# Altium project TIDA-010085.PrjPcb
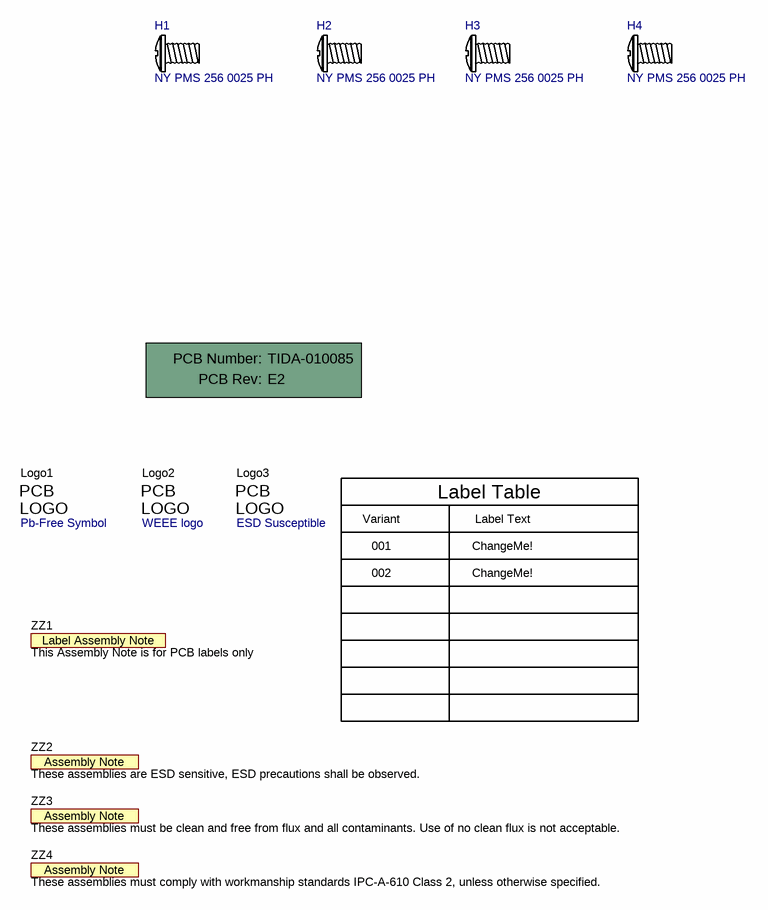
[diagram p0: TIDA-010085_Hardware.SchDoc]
CopyrightYear: 2021; EVM_orderable: N/A; PCB_Layout: Manu; PCB_Rev: E2; PRJ_Customer: Public Release; PRJ_Engineer: Manu Balakrishnan; PRJ_Number: TIDA-010085; PRJ_Title: 24-VAC Multi-channel Solid State Relay; SCH_Rev: E2; TechSupport: http://www.ti.com/support; TID: 010085
4 sheets, 249 parts. Net scope: flat (ports and power ports of the same name join across sheets).
Board file: TIDA-010085.PcbDoc
Sheets:
  TIDA-010085_CoverSheet.SchDoc
  TIDA-010085_Hardware.SchDoc
  TIDA-010085_Page1.SchDoc
  TIDA-010085_Page2.SchDoc

## Sheet TIDA-010085_CoverSheet.SchDoc
size 431 x 279 mm; Date: Not shown in title block; ApprovedBy: Not shown in title block; CheckedBy: Not shown in title block; Author: Not shown in title block; CompanyName: Not shown in title block; DrawnBy: Manu; Engineer: Not shown in title block; Organization: Not shown in title block; Address1: Not shown in title block; Address2: Not shown in title block; Address3: Not shown in title block; Address4: Not shown in title block; DocumentNumber: 1; Revision: Use project parameter SCH_Rev; SheetNumber: 1; SheetTotal: 4; PageSetup: Record=PageOptions¦CenterHorizontal=True¦CenterVertical=True¦PrintScale=1.00¦XCorrection=1.00¦YCorrection=1.00¦PrintKind=0¦BorderSize=5000000¦LeftOffset=0¦BottomOffset=0¦Orientation=2¦PaperLength=1000¦PaperWidth=1000¦Scale=100¦PaperSource=15¦PrintQuality=600¦MediaType=1¦DitherType=10¦PaperKind=Letter¦PrintScaleMode=1

## Sheet TIDA-010085_Hardware.SchDoc
size 431 x 279 mm; Date: Not shown in title block; ApprovedBy: Not shown in title block; CheckedBy: Not shown in title block; Author: Not shown in title block; CompanyName: Not shown in title block; DrawnBy: Manu; Engineer: Not shown in title block; Organization: Not shown in title block; Address1: Not shown in title block; Address2: Not shown in title block; Address3: Not shown in title block; Address4: Not shown in title block; DocumentNumber: 1; Revision: Use project parameter SCH_Rev; SheetNumber: 4; SheetTotal: 4; PageSetup: Record=PageOptions¦CenterHorizontal=True¦CenterVertical=True¦PrintScale=1.00¦XCorrection=1.00¦YCorrection=1.00¦PrintKind=0¦BorderSize=5000000¦LeftOffset=0¦BottomOffset=0¦Orientation=2¦PaperLength=1000¦PaperWidth=1000¦Scale=100¦PaperSource=15¦PrintQuality=600¦MediaType=1¦DitherType=10¦PaperKind=Letter¦PrintScaleMode=1

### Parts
!PCB1  Printed Circuit Board  (value not drawn)  (mechanical)
H1  NY PMS 256 0025 PH  [NY PMS 256 0025 PH]
H2  NY PMS 256 0025 PH  [NY PMS 256 0025 PH]
H3  NY PMS 256 0025 PH  [NY PMS 256 0025 PH]
H4  NY PMS 256 0025 PH  [NY PMS 256 0025 PH]
Logo1  Pb-Free Symbol  [Pb-Free_Overlay_Small]  (no BOM)
Logo2  WEEE logo  [WEEE_Minimum]  (no BOM)
Logo3  ESD Susceptible  [ESD_Overlay_Small]  (no BOM)
ZZ1  This Assembly Note is for PCB labels only  [AssemblyNoteLabel]  (no BOM)
ZZ2  These assemblies are ESD sensitive, ESD precautions shall be observed.  [AssemblyNote]  (no BOM)
ZZ3  These assemblies must be clean and free from flux and all contaminants. Use of no clean flux is not acceptable.  [AssemblyNote]  (no BOM)
ZZ4  These assemblies must comply with workmanship standards IPC-A-610 Class 2, unless otherwise specified.  [AssemblyNote]  (no BOM)

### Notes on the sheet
- Variant
- 001
- Label Table
- Label Text
- ChangeMe!
- 002

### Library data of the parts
!PCB1 = PCB: Manufacturer: Any; PartNumber: TIDA-010085; SymbolCreator: a0412235
H1-H4 = CMP-0003709-1: MACHINE SCREW PAN PHILLIPS 2-56; Manufacturer: B&F Fastener Supply; CompType: Hardware
Logo1 = CMP-0074839-1: SymbolCreator: a0412235
Logo2 = CMP-0074769-1
Logo3 = CMP-0074840-1: ESD Susceptible Symbol; SymbolCreator: a0412235; Lib Reference: ESD_Susceptible
ZZ1 = AssemblyNoteLabel: SymbolCreator: a0412235
ZZ2-ZZ4 = AssemblyNote: SymbolCreator: codlsc

## Sheet TIDA-010085_Page1.SchDoc
size 431 x 279 mm; Date: Not shown in title block; ApprovedBy: Not shown in title block; CheckedBy: Not shown in title block; Author: Not shown in title block; CompanyName: Not shown in title block; DrawnBy: Manu; Engineer: Not shown in title block; Organization: Not shown in title block; Address1: Not shown in title block; Address2: Not shown in title block; Address3: Not shown in title block; Address4: Not shown in title block; DocumentNumber: 1; Revision: Use project parameter SCH_Rev; SheetNumber: 2; SheetTotal: 4; PageSetup: Record=PageOptions¦CenterHorizontal=True¦CenterVertical=True¦PrintScale=1.00¦XCorrection=1.00¦YCorrection=1.00¦PrintKind=0¦BorderSize=5000000¦LeftOffset=0¦BottomOffset=0¦Orientation=2¦PaperLength=1000¦PaperWidth=1000¦Scale=100¦PaperSource=15¦PrintQuality=600¦MediaType=1¦DitherType=10¦PaperKind=Letter¦PrintScaleMode=1
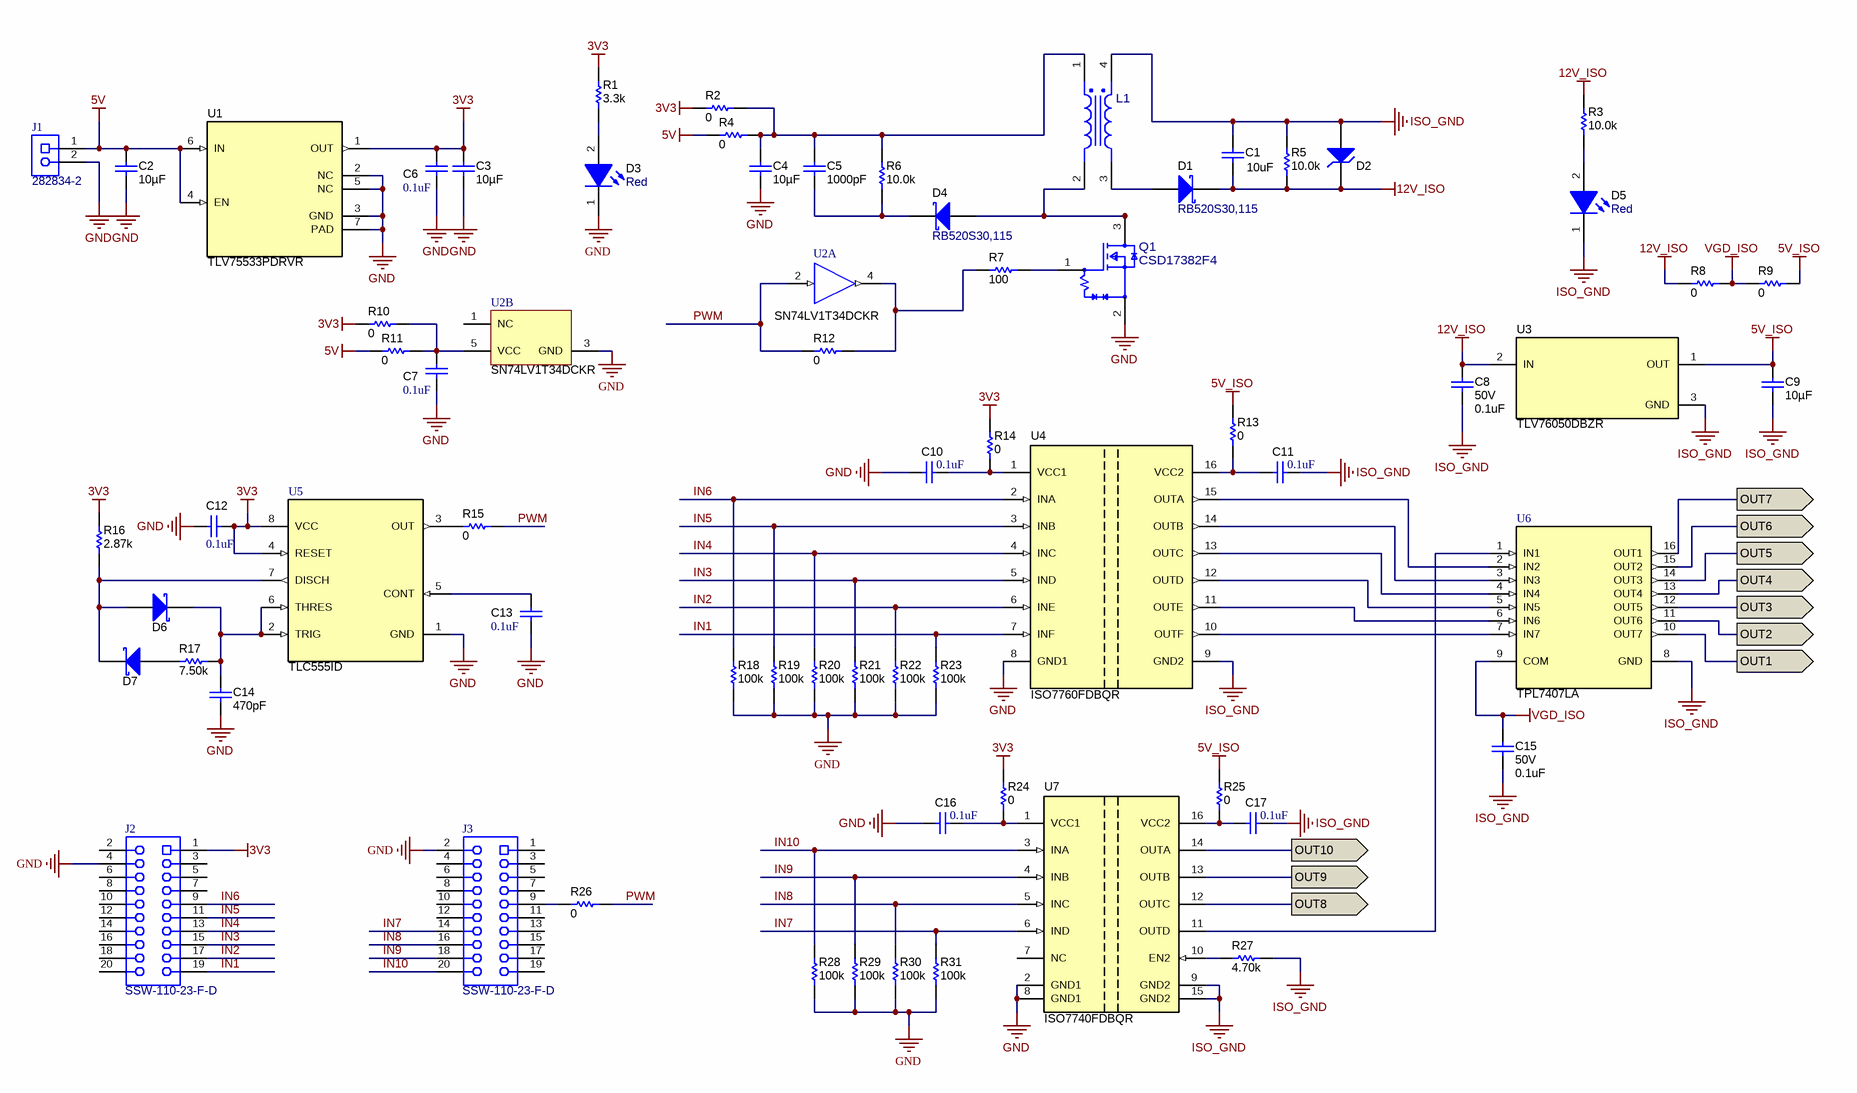
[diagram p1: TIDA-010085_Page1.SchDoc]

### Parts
C1  ValueDisplayed: 10uF  [0603]  (hidden comment: GRM188R61E106MA73D)
C2  ValueDisplayed: 10µF  [0603]  (hidden comment: GRM188R61A106KE69D)
C3  ValueDisplayed: 10µF  [0603]  (hidden comment: GRM188R61A106KE69D)
C4  ValueDisplayed: 10µF  [0603]  (hidden comment: GRM188R61A106KE69D)
C5  ValueDisplayed: 1000pF  [0402]  (hidden comment: 885012205061)
C6  ValueDisplayed: 0.1uF  [0402]  (hidden comment: GCM155R71A104KA55D)
C7  ValueDisplayed: 0.1uF  [0402]  (hidden comment: GCM155R71A104KA55D)
C8  VDC_V: 50V  ValueDisplayed: 0.1uF  [0402]  (hidden comment: GRM155R71H104ME14D)
C9  ValueDisplayed: 10µF  [0603]  (hidden comment: GRM188R61A106KE69D)
C10  ValueDisplayed: 0.1uF  [0402]  (hidden comment: GCM155R71A104KA55D)
C11  ValueDisplayed: 0.1uF  [0402]  (hidden comment: GCM155R71A104KA55D)
C12  ValueDisplayed: 0.1uF  [0402]  (hidden comment: GCM155R71A104KA55D)
C13  ValueDisplayed: 0.1uF  [0402]  (hidden comment: GCM155R71A104KA55D)
C14  ValueDisplayed: 470pF  [0402]  (hidden comment: GRT155R71H471KE01D)
C15  VDC_V: 50V  ValueDisplayed: 0.1uF  [0402]  (hidden comment: GRM155R71H104ME14D)
C16  ValueDisplayed: 0.1uF  [0402]  (hidden comment: GCM155R71A104KA55D)
C17  ValueDisplayed: 0.1uF  [0402]  (hidden comment: GCM155R71A104KA55D)
D1  RB520S30,115  [SOD-523]
D2  BZT585B12T-7  [SOD-523]  (value not drawn)
D3  value Red  [WL-SMCW_RED]  (hidden comment: 150060RS75000)
D4  RB520S30,115  [SOD-523]
D5  value Red  [WL-SMCW_RED]  (hidden comment: 150060RS75000)
D6  RB520S30,115  [SOD-523]  (value not drawn)
D7  RB520S30,115  [SOD-523]  (value not drawn)
J1  282834-2  [TEC_282834-2]
J2  SSW-110-23-F-D  [CONN_SSW-110-23-F-D]
J3  SSW-110-23-F-D  [CONN_SSW-110-23-F-D]
L1  744889030330  [FP-744889020330_SMD4-MFG]  (value not drawn)
Q1  CSD17382F4  [FP-CSD17382F4_PICOSTAR3-MFG]
R1  ValueDisplayed: 3.3k  [0402]  (hidden comment: CRCW04023K30JNED)
R2  ValueDisplayed: 0  [0402]  (hidden comment: RC0402JR-070RL)
R3  ValueDisplayed: 10.0k  [0402]  (hidden comment: RMCF0402FT10K0)
R4  ValueDisplayed: 0  [0402]  (hidden comment: RC0402JR-070RL)
R5  ValueDisplayed: 10.0k  [0402]  (hidden comment: RMCF0402FT10K0)
R6  ValueDisplayed: 10.0k  [0402]  (hidden comment: RMCF0402FT10K0)
R7  ValueDisplayed: 100  [0402]  (hidden comment: RC0402FR-07100RL)
R8  ValueDisplayed: 0  [0402]  (hidden comment: RC0402JR-070RL)
R9  ValueDisplayed: 0  [0402]  (hidden comment: RC0402JR-070RL)
R10  ValueDisplayed: 0  [0402]  (hidden comment: RC0402JR-070RL)
R11  ValueDisplayed: 0  [0402]  (hidden comment: RC0402JR-070RL)
R12  ValueDisplayed: 0  [0402]  (hidden comment: RC0402JR-070RL)
R13  ValueDisplayed: 0  [0402]  (hidden comment: RC0402JR-070RL)
R14  ValueDisplayed: 0  [0402]  (hidden comment: RC0402JR-070RL)
R15  ValueDisplayed: 0  [0402]  (hidden comment: RC0402JR-070RL)
R16  ValueDisplayed: 2.87k  [0402]  (hidden comment: CRCW04022K87FKED)
R17  ValueDisplayed: 7.50k  [0402]  (hidden comment: CRCW04027K50FKED)
R18  ValueDisplayed: 100k  [0402]  (hidden comment: ERJ-2RKF1003X)
R19  ValueDisplayed: 100k  [0402]  (hidden comment: ERJ-2RKF1003X)
R20  ValueDisplayed: 100k  [0402]  (hidden comment: ERJ-2RKF1003X)
R21  ValueDisplayed: 100k  [0402]  (hidden comment: ERJ-2RKF1003X)
R22  ValueDisplayed: 100k  [0402]  (hidden comment: ERJ-2RKF1003X)
R23  ValueDisplayed: 100k  [0402]  (hidden comment: ERJ-2RKF1003X)
R24  ValueDisplayed: 0  [0402]  (hidden comment: RC0402JR-070RL)
R25  ValueDisplayed: 0  [0402]  (hidden comment: RC0402JR-070RL)
R26  ValueDisplayed: 0  [0402]  (hidden comment: RC0402JR-070RL)
R27  ValueDisplayed: 4.70k  [0402]  (hidden comment: RC0402FR-074K7L)
R28  ValueDisplayed: 100k  [0402]  (hidden comment: ERJ-2RKF1003X)
R29  ValueDisplayed: 100k  [0402]  (hidden comment: ERJ-2RKF1003X)
R30  ValueDisplayed: 100k  [0402]  (hidden comment: ERJ-2RKF1003X)
R31  ValueDisplayed: 100k  [0402]  (hidden comment: ERJ-2RKF1003X)
U1  TLV75533PDRVR  [DRV0006A]
U2  SN74LV1T34DCKR  [DCK0005A_N]  (parts A,B of 2)
U3  TLV76050DBZR  [DBZ0003A_N]
U4  ISO7760FDBQR  [DBQ0016A_N]
U5  PartNumber: TLC555ID  [D0008A_N]  (hidden comment: TLC555CD)
U6  PartNumber: TPL7407LA  [PW0016A_L]  (hidden comment: TPL7407LPWR)
U7  ISO7740FDBQR  [DBQ0016A_N]

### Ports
OUT1 (out), OUT2 (out), OUT3 (out), OUT4 (out), OUT5 (out), OUT6 (out), OUT7 (out), OUT8 (out), OUT9 (out), OUT10 (out)

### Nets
3V3: C3.1 C6.1 C12.2 J2.1 R1.2 R2.1 R10.1 R14.2 R16.2 R24.2 U1.1(OUT) U5.4(RESET) U5.8(VCC)
5V: C2.1 J1.1 R4.1 R11.1 U1.4(EN) U1.6(IN)
5V_ISO: C9.1 R9.2 R13.2 R25.2 U3.1(OUT)
12V_ISO: C1.2 C8.1 D1.1(K) D2.1(K) R3.2 R5.1 R8.1 U3.2(IN)
GND: C2.2 C3.2 C4.2 C6.2 C7.2 C10.1 C12.1 C13.2 C14.2 C16.1 D3.1(K) J1.2 J2.4 J3.2 Q1.2(S) R18.1 R19.1 R20.1 R21.1 R22.1 R23.1 R28.1 R29.1 R30.1 R31.1 U1.2(NC) U1.3(GND) U1.5(NC) U1.7(PAD) U2.3(GND) U4.8(GND1) U5.1(GND) U7.2(GND1) U7.8(GND1)
ISO_GND: C1.1 C8.2 C9.2 C11.2 C15.2 C17.2 D2.2(A) D5.1(K) L1.4 R5.2 R27.2 U3.3(GND) U4.9(GND2) U6.8(GND) U7.9(GND2) U7.15(GND2)
VGD_ISO: C15.1 R8.2 R9.1 U6.9(COM)
IN1: J2.19 R23.2 U4.7(INF)
IN2: J2.17 R22.2 U4.6(INE)
IN3: J2.15 R21.2 U4.5(IND)
IN4: J2.13 R20.2 U4.4(INC)
IN5: J2.11 R19.2 U4.3(INB)
IN6: J2.9 R18.2 U4.2(INA)
IN7: J3.14 R31.2 U7.6(IND)
IN8: J3.16 R30.2 U7.5(INC)
IN9: J3.18 R29.2 U7.4(INB)
IN10: J3.20 R28.2 U7.3(INA)
OUT1: U6.10(OUT7) ; port OUT1
OUT2: U6.11(OUT6) ; port OUT2
OUT3: U6.12(OUT5) ; port OUT3
OUT4: U6.13(OUT4) ; port OUT4
OUT5: U6.14(OUT3) ; port OUT5
OUT6: U6.15(OUT2) ; port OUT6
OUT7: U6.16(OUT1) ; port OUT7
OUT8: U7.12(OUTC) ; port OUT8
OUT9: U7.13(OUTB) ; port OUT9
OUT10: U7.14(OUTA) ; port OUT10
PWM: R12.1 R15.2 R26.2 U2.2(A)
NetC4_1: C4.1 C5.1 L1.1 R2.2 R4.2 R6.2
NetC5_2: C5.2 D4.1(K) R6.1
NetC7_1: C7.1 R10.2 R11.2 U2.5(VCC)
NetC10_2: C10.2 R14.1 U4.1(VCC1)
NetC11_1: C11.1 R13.1 U4.16(VCC2)
NetC13_1: C13.1 U5.5(CONT)
NetC14_1: C14.1 D6.1(K) R17.2 U5.2(TRIG) U5.6(THRES)
NetC16_2: C16.2 R24.1 U7.1(VCC1)
NetC17_1: C17.1 R25.1 U7.16(VCC2)
NetD1_2: D1.2(A) L1.3
NetD3_2: D3.2(A) R1.1
NetD4_2: D4.2(A) L1.2 Q1.3(D)
NetD5_2: D5.2(A) R3.1
NetD6_2: D6.2(A) D7.1(K) R16.1 U5.7(DISCH)
NetD7_2: D7.2(A) R17.1
NetJ3_9: J3.9 R26.1
NetQ1_1: Q1.1(G) R7.2
NetR7_1: R7.1 R12.2 U2.4(Y)
NetR15_1: R15.1 U5.3(OUT)
NetR27_1: R27.1 U7.10(EN2)
NetU4_10: U4.10(OUTF) U6.7(IN7)
NetU4_11: U4.11(OUTE) U6.6(IN6)
NetU4_12: U4.12(OUTD) U6.5(IN5)
NetU4_13: U4.13(OUTC) U6.4(IN4)
NetU4_14: U4.14(OUTB) U6.3(IN3)
NetU4_15: U4.15(OUTA) U6.2(IN2)
NetU6_1: U6.1(IN1) U7.11(OUTD)

Not connected (* = marked no-connect by the designer): J2 2 3 5 6 7 8 10 12 14 16 18 20; J3 1 3 4 5 6 7 8 10 11 12 13 15 17 19; U2 1(NC); U7 7(NC)

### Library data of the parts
C1 = CMP-0007344-5: CAP, CERM, 10 uF, 25 V, +/- 20%, X5R, 0603; Manufacturer: MuRata; TaMin_C: -55°C; Polarized: N; SizeAreaWB_mm2: 4.68; Value1: Unknown; U/M: EA; Value: 10uF; TaMax_C: 85°C; SizeZ_mm: 1; SizeX_mm: 1.6; SizeY_mm: 0.8; Value2: 25V; SizeArea_mm2: 1.28; Cap_F: 10µF; AEC Category: Q200
C2-C4 C9 = CMP-0085855-1: CAP, CERM, 10 µF, 10 V,+/- 10%, X5R, 0603; Manufacturer: MuRata; SizeX_mm: 1.6; Value2: 10V; SizeAreaWB_mm2: 4.68; Green_REACh: Incomplete; AEC Category: Q200; SizeArea_mm2: 1.28; SizeY_mm: 0.8; Green_Lifecycle: Active; TaMax_C: 85°C; Value: 10uF; U/M: EA; Polarized: N; TaMin_C: -55°C; SizeZ_mm: 1
C5 = CMP-0006231-2: CAP, CERM, 1000 pF, 50 V, +/- 10%, X7R, 0402; Manufacturer: Wurth Elektronik; TaMin_C: -55°C; Polarized: N; SizeAreaWB_mm2: 3; Value1: Unknown; U/M: EA; Value: 1000pF; TaMax_C: 125°C; SizeZ_mm: 0.6; SizeX_mm: 1; SizeY_mm: 0.5; Value2: 50V; Cap_F: 1nF; AEC Category: Q200
C6 C7 C10-C13 C16 C17 = CMP-0006350-2: CAP, CERM, 0.1 uF, 10 V, +/- 10%, X7R, AEC-Q200 Grade 1, 0402; Manufacturer: MuRata; TaMin_C: -55°C; Polarized: N; SizeAreaWB_mm2: 3; Value1: Unknown; U/M: EA; Value: 0.1uF; TaMax_C: 125°C; SizeZ_mm: 0.6; SizeX_mm: 1; SizeY_mm: 0.5; Value2: 10V; AEC Qualified: Y; Cap_F: 100nF; AEC Category: Q200
C8 C15 = CMP-0006675-2: CAP, CERM, 0.1 uF, 50 V, +/- 20%, X7R, 0402; Manufacturer: MuRata; TaMin_C: -55°C; Polarized: N; SizeAreaWB_mm2: 3; Value1: Unknown; U/M: EA; Value: 0.1uF; TaMax_C: 125°C; SizeZ_mm: 0.6; SizeX_mm: 1; SizeY_mm: 0.5; Cap_F: 100nF; AEC Category: Q200
C14 = CMP-0860801-1: CAP, CERM, 470 pF, 50 V,+/- 10%, X7R, AEC-Q200 Grade 1, 0402; Manufacturer: MuRata; SizeArea_mm2: 0.5; Value: 470pF; SizeAreaWB_mm2: 3; AEC Qualified: Y; VDC_V: 50V; TaMax_C: 125°C; TaMin_C: -55°C; U/M: EA; SizeZ_mm: 0.6; AEC Grade: 1; AEC Category: Q200; Polarized: N
D1 D4 D6 D7 = CMP-0028609-3: Diode, Schottky, 30 V, 0.2 A, SOD-523; Manufacturer: Nexperia; SizeArea_mm2: 1.53; SizeZ_mm: 0.65; AEC Category: Q101; Vr_V: 30V; SizeAreaWB_mm2: 5.13; Value2: 0.6V; Io_A: 200mA; SizeX_mm: 1.7; TJmax_C: 150°C; SizeY_mm: 0.9; Green_Lifecycle: Not Set; Green_REACh: Incomplete; Vf_V: 600mV; Value: 30V; Value1: 0.2A
D2 = CMP-0005888-2: DIODE ZENER 12V 350MW SOD523; Manufacturer: Diodes Inc.; SizeAreaWB_mm2: 5.13; Value1: 0.35W; RJA_CperW: 357; U/M: EA; SizeZ_mm: 0.65; SizeX_mm: 1.7; SizeY_mm: 0.9; SizeArea_mm2: 1.53; AEC Qualified: Y; AEC Category: Q101
D3 D5 = CMP-0002947-1: LED, Red, SMD; Manufacturer: Wurth Elektronik; Io_A: 30mA; Power_TotalModule: 72mW; Vr_V: 5V; Tjmax_C: 85°C; Value1: 0.072W; U/M: EA; Angle: 140; Vf_V: 2V; Type: AlInGaP
J1 = CMP-0054974-1: Terminal Block, 2x1, 2.54mm, TH; Manufacturer: TE Connectivity; CNHeader: FALSE; Green_Lifecycle: Active; Green_REACh: Passed; CT: TRUE
J2 J3 = CMP-0075442-1: Connector, Receptacle, 100mil, 10x2, Gold plated, TH; Manufacturer: Samtec; Green_Lifecycle: Active; CompType: Socket Strip; Green_REACh: Passed; CT: True; CNHeader: False
L1 = CMP-0090423-1: Shielded 2 Coil Inductor Array Inductance - Connected in Series 33µH Inductance - Connected in Parallel 5.2Ohm DC Resistance (DCR) - Parallel 0.45A Nonstandard; Manufacturer: Wurth Electronics; Ns1toNp: 1:3; AEC Qualified: No; TaMin_C: -40°C; DCR_ohm: 1.9; SizeZ_mm: 3.1mm; TaMax_C: +85°C; Rsec1_ohm: 5200mΩ
Q1 = CMP-0086436-1: N-Channel 30V 2.3A (Ta) 500mW (Ta) Surface Mount 3-PICOSTAR; Manufacturer: Texas Instruments; Rdson45_ohm: 0.056; Vgs_V: 10V; SizeZ_mm: 0.35mm; QgTyp_nC: 2.1nC @ 15V; AEC Qualified: No; ChMode: False
R1 = CMP-0026918-5: RES, 3.3 k, 5%, 0.063 W, AEC-Q200 Grade 0, 0402; Manufacturer: Vishay-Dale; Power_W: 63mW; TempCo: 200 ppm/C; Value_Code: 3k30; Value: 3.3k; EIA_Code: E24; SizeX_mm: 1; SizeY_mm: 0.5; SizeZ_mm: 0.6; Value2: 0.063W; AEC Qualified: Y; VDC_V: 50V; AEC Category: Q200; AEC Grade: 0
R2 R4 R8-R15 R24-R26 = CMP-0027004-2: RES, 0, 5%, 0.063 W, 0402; Manufacturer: Yageo America; Power_W: 63mW; TempCo: 200 ppm/C; Value_Code: 0000; U/M: EA; Value: 0; EIA_Code: E24; SizeX_mm: 1; SizeY_mm: 0.5; SizeZ_mm: 0.6; Value2: 0.063W; VDC_V: 50V; AEC Category: Q200
R3 R5 R6 = CMP-0026754-1: RES, 10.0 k, 1%, 0.063 W, AEC-Q200 Grade 0, 0402; Manufacturer: Stackpole Electronics Inc; Power_W: 63mW; TempCo: 100 ppm/C; Value_Code: 10k0; U/M: EA; Value: 10.0k; EIA_Code: E96; Res_ohm: 10k; SizeX_mm: 1; SizeY_mm: 0.5; SizeZ_mm: 0.6; Value2: 0.063W; AEC Qualified: Y; VDC_V: 50V; AEC Grade: 0; AEC Category: Q200
R7 = CMP-0026722-1: RES, 100, 1%, 0.063 W, 0402; Manufacturer: Yageo America; Power_W: 63mW; TempCo: 100 ppm/C; Value_Code: 100R; U/M: EA; Value: 100; EIA_Code: E96; SizeX_mm: 1; SizeY_mm: 0.5; SizeZ_mm: 0.6; Value2: 0.063W; AEC Qualified: N; VDC_V: 50V; AEC Category: Q200
R16 = CMP-0026243-2: RES, 2.87 k, 1%, 0.063 W, AEC-Q200 Grade 0, 0402; Manufacturer: Vishay-Dale; Power_W: 63mW; TempCo: 100 ppm/C; Value_Code: 2k87; Value: 2.87k; EIA_Code: E96; SizeX_mm: 1; SizeY_mm: 0.5; SizeZ_mm: 0.6; Value2: 0.063W; AEC Qualified: Y; VDC_V: 50V; AEC Category: Q200; AEC Grade: 0
R17 = CMP-0026555-2: RES, 7.50 k, 1%, 0.063 W, AEC-Q200 Grade 0, 0402; Manufacturer: Vishay-Dale; Power_W: 63mW; TempCo: 100 ppm/C; Value_Code: 7k50; Value: 7.50k; EIA_Code: E96; Res_ohm: 7.5k; SizeX_mm: 1; SizeY_mm: 0.5; SizeZ_mm: 0.6; Value2: 0.063W; AEC Qualified: Y; VDC_V: 50V; AEC Category: Q200; AEC Grade: 0
R18-R23 R28-R31 = CMP-0026659-1: RES, 100 k, 1%, 0.1 W, 0402; Manufacturer: Panasonic; Power_W: 100mW; TempCo: 100 ppm/C; U/M: EA; Value: 100k; EIA_Code: E96; SizeX_mm: 1; SizeY_mm: 0.5; SizeZ_mm: 0.6; Value2: 0.1W; VDC_V: 50V; AEC Category: Q200
R27 = CMP-0026739-1: RES, 4.70 k, 1%, 0.0625 W, 0402; Manufacturer: Yageo America; Power_W: 62.5mW; TempCo: 100 ppm/C; Value_Code: 4k70; U/M: EA; Value: 4.70k; Res_ohm: 4.7k; SizeX_mm: 1; SizeY_mm: 0.5; SizeZ_mm: 0.6; AEC Qualified: N; VDC_V: 50V; AEC Category: Q200
U1 = CMP-0013427-7: 500mA LDO, DRV0006A (WSON-6); Manufacturer: Texas Instruments; SizeX_mm: 2; CompType: IC; SizeZ_mm: 0.8; SizeArea_mm2: 4; SizeAreaWB_mm2: 9; U/M: EA
U2 = CMP-0051718-3: Single Power Supply BUFFER Logic Level Shifter (no enable), DCK0005A (SOT-SC70-5); Manufacturer: Texas Instruments; 3-State Output: Yes; Sub-Family: Non-Inverting Buffer/Driver; Rating: Catalog; ICC @ Nom Voltage(Max)(mA): 0.01; Logic: True; tpd @ Nom Voltage(Max)(ns): 14.5,9.5,8.0,6.5; Output Type: CMOS; VCC(Max)(V): 5.5; Voltage(Nom)(V): 1.8,2.5,3.3,5.5; Bits(#): 1; Output Drive (IOL/IOH)(Max)(mA): 8/-8; F @ Nom Voltage(Max)(Mhz): 50; Special Features: 1.8V to 3.3V Up Translation,3.3V to 1.8V Down Translation,5V Input Tolerant; Input Type: TTL; Technology Family: LV1T; VCC(Min)(V): 1.6; AEC Category: Q200; AEC Qualified: N; CompType: IC; SizeAreaWB_mm2: 9.3; SizeArea_mm2: 4.2; SizeX_mm: 2.1; SizeY_mm: 2.0; SizeZ_mm: 1.1
U3 = CMP-0074892-1: 100-mA, 30-V, Fixed-Output, Linear-Voltage Regulator, DBZ0003A (SOT-23-3); Alternate PartNumber: TLV76050DBZT; Alternate Manufacturer: Texas Instruments; SizeAreaWB_mm2: 14.0; SizeZ_mm: 1.12; SizeX_mm: 2.5; SizeY_mm: 3.0; SizeArea_mm2: 7.5; CompType: IC; AEC Qualified: N; AEC Category: Q200
U4 = CMP-0860872-1: High-speed, robust EMC six-channel digital isolator, DBQ0016A (SSOP-16); Manufacturer: Texas Instruments; SizeY_mm: 10; AEC Category: Q200; CompType: IC; SizeX_mm: 6; Rating: Catalog; AEC Qualified: N; SizeArea_mm2: 60; SizeZ_mm: 1.75; SizeAreaWB_mm2: 96
U5 = CMP-0065673-1: 2.1-MHz, 250-uA, Low-Power Timer, D0008A (SOIC-8); Alternate Manufacturer: Texas Instruments; Green_Lifecycle: Active; SizeAreaWB_mm2: 56.58; Green_REACh: Passed; U/M: EA; SizeZ_mm: 1.75; SizeX_mm: 4.9; SizeY_mm: 6.2; SizeArea_mm2: 30.38; CompType: IC
U6 = CMP-0033666-1: 7-Channel Low Side Driver, 0 to 40 V VOUT, -40 to 125 degC, 16-Pin TSSOP (PW), RoHS, Tape and Reel; Packing: TRUE; VCOM Min: 8.5 V; VOUT Min: 0 V; VOUT Max: 40 V; CI: 5 pF
U7 = CMP-0084705-1: High-Speed, Low-Power, Robust EMC Quad-Channel Digital Isolator, DBQ0016A (SSOP-16); Alternate Manufacturer: Texas Instruments; SizeZ_mm: 1.75; CompType: IC; SizeArea_mm2: 60; SizeX_mm: 6; SizeAreaWB_mm2: 96; Rating: Catalog; AEC Category: Q200; SizeY_mm: 10; AEC Qualified: N

## Sheet TIDA-010085_Page2.SchDoc
size A2; Date: Not shown in title block; ApprovedBy: Not shown in title block; CheckedBy: Not shown in title block; Author: Not shown in title block; CompanyName: Not shown in title block; Engineer: Not shown in title block; Organization: Not shown in title block; Address1: Not shown in title block; Address2: Not shown in title block; Address3: Not shown in title block; Address4: Not shown in title block; DocumentNumber: 2; Revision: Use project parameter SCH_Rev; SheetNumber: 3; SheetTotal: 4; PageSetup: Record=PageOptions¦CenterHorizontal=True¦CenterVertical=True¦PrintScale=1.00¦XCorrection=1.00¦YCorrection=1.00¦PrintKind=0¦BorderSize=5000000¦LeftOffset=0¦BottomOffset=0¦Orientation=2¦PaperLength=1000¦PaperWidth=1000¦Scale=100¦PaperSource=15¦PrintQuality=600¦MediaType=1¦DitherType=10¦PaperKind=Letter¦PrintScaleMode=1
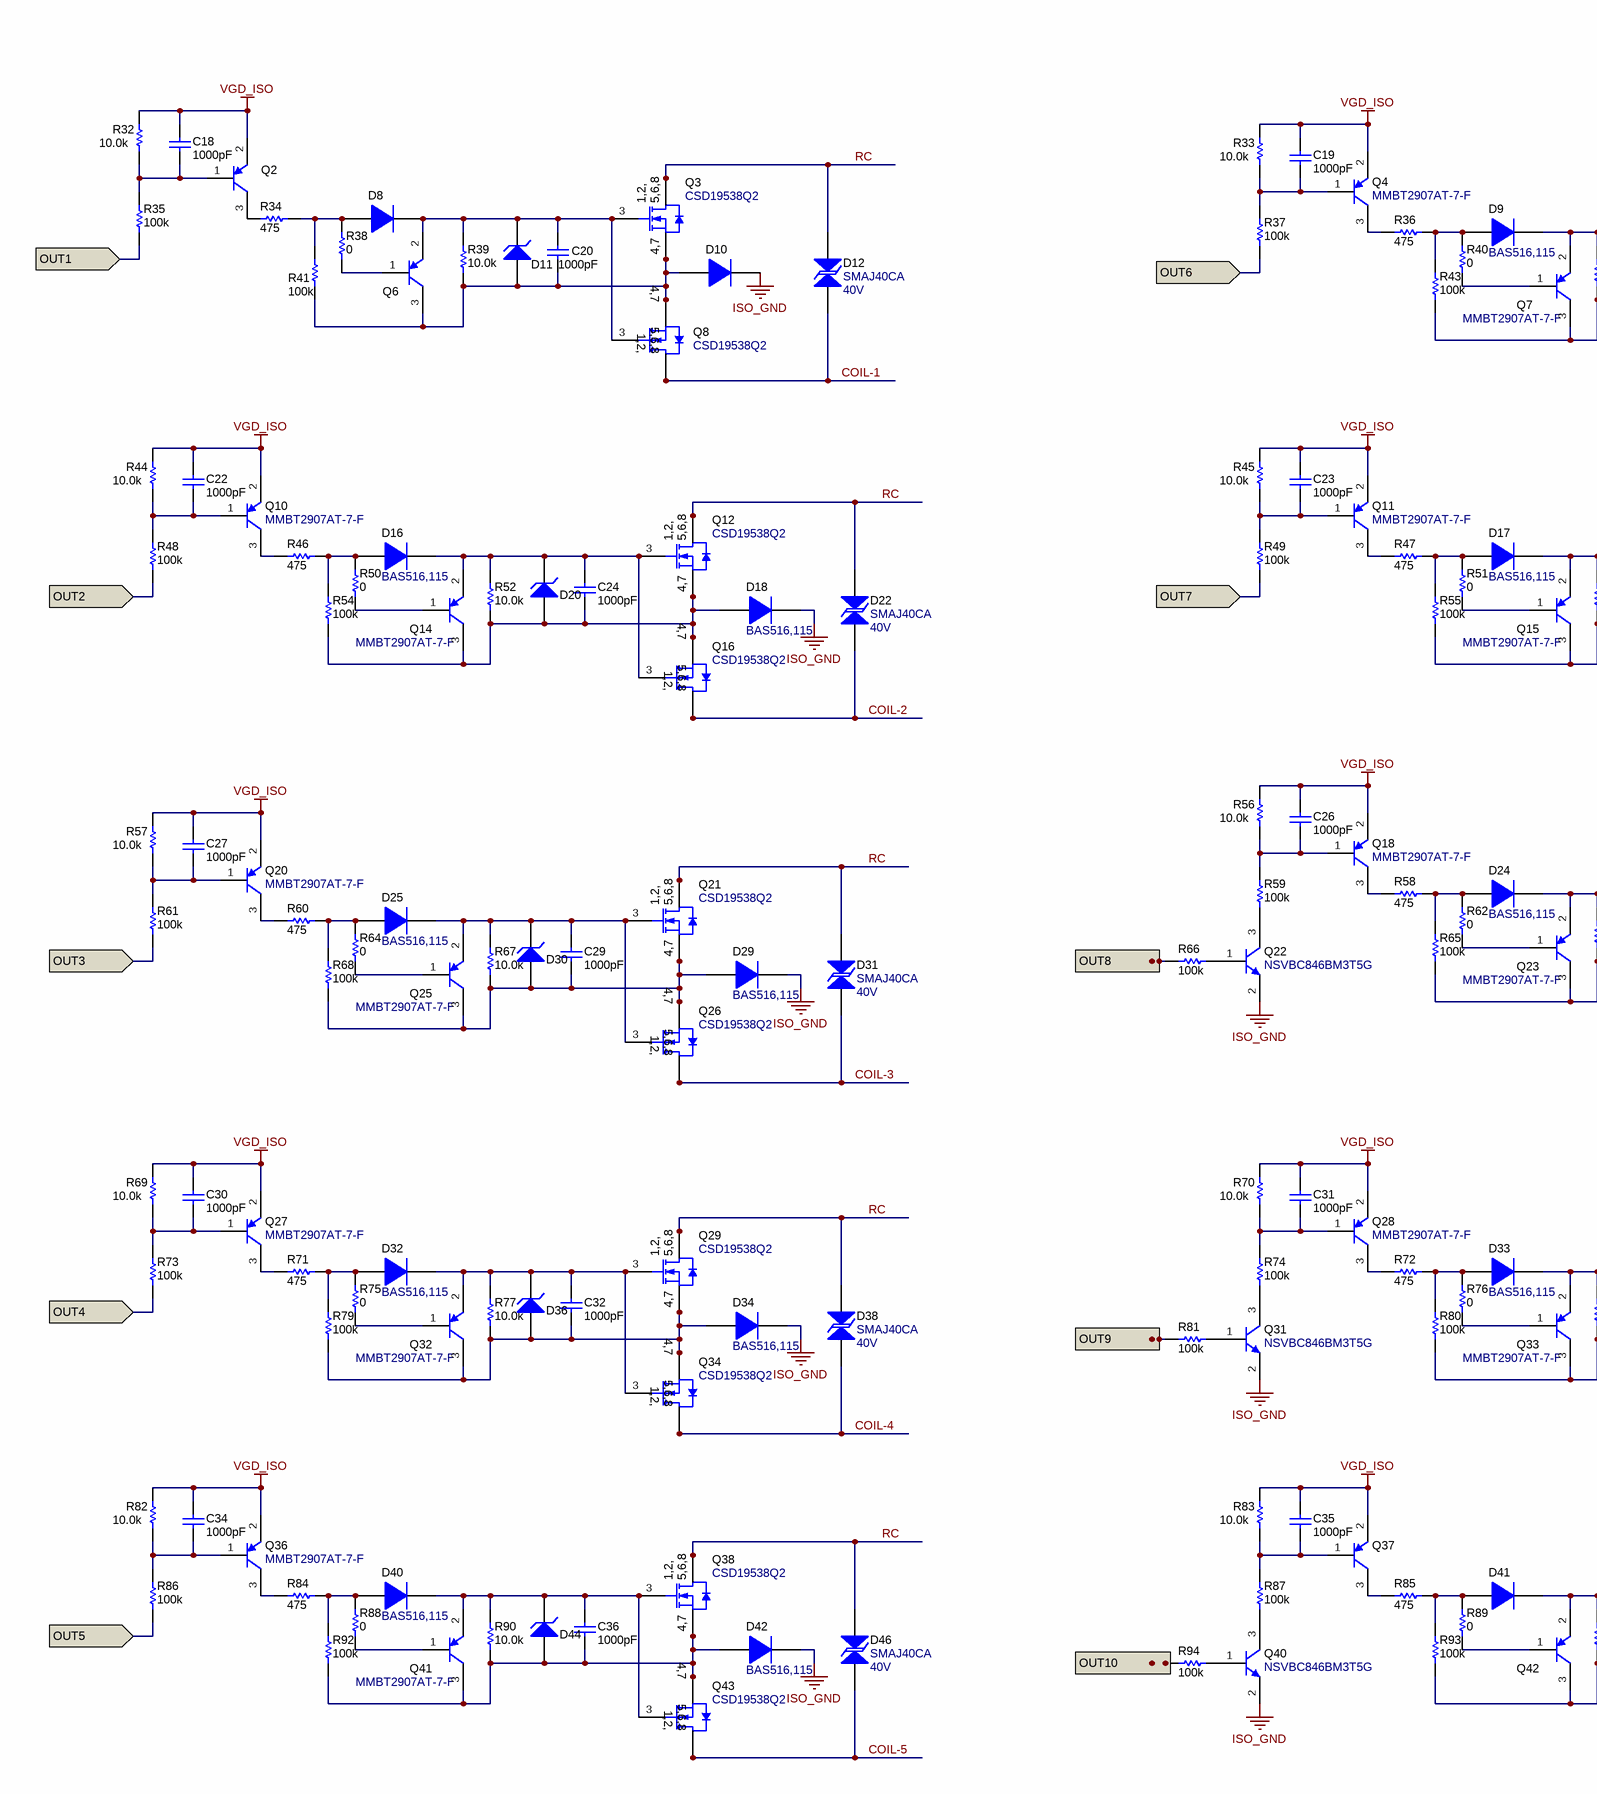
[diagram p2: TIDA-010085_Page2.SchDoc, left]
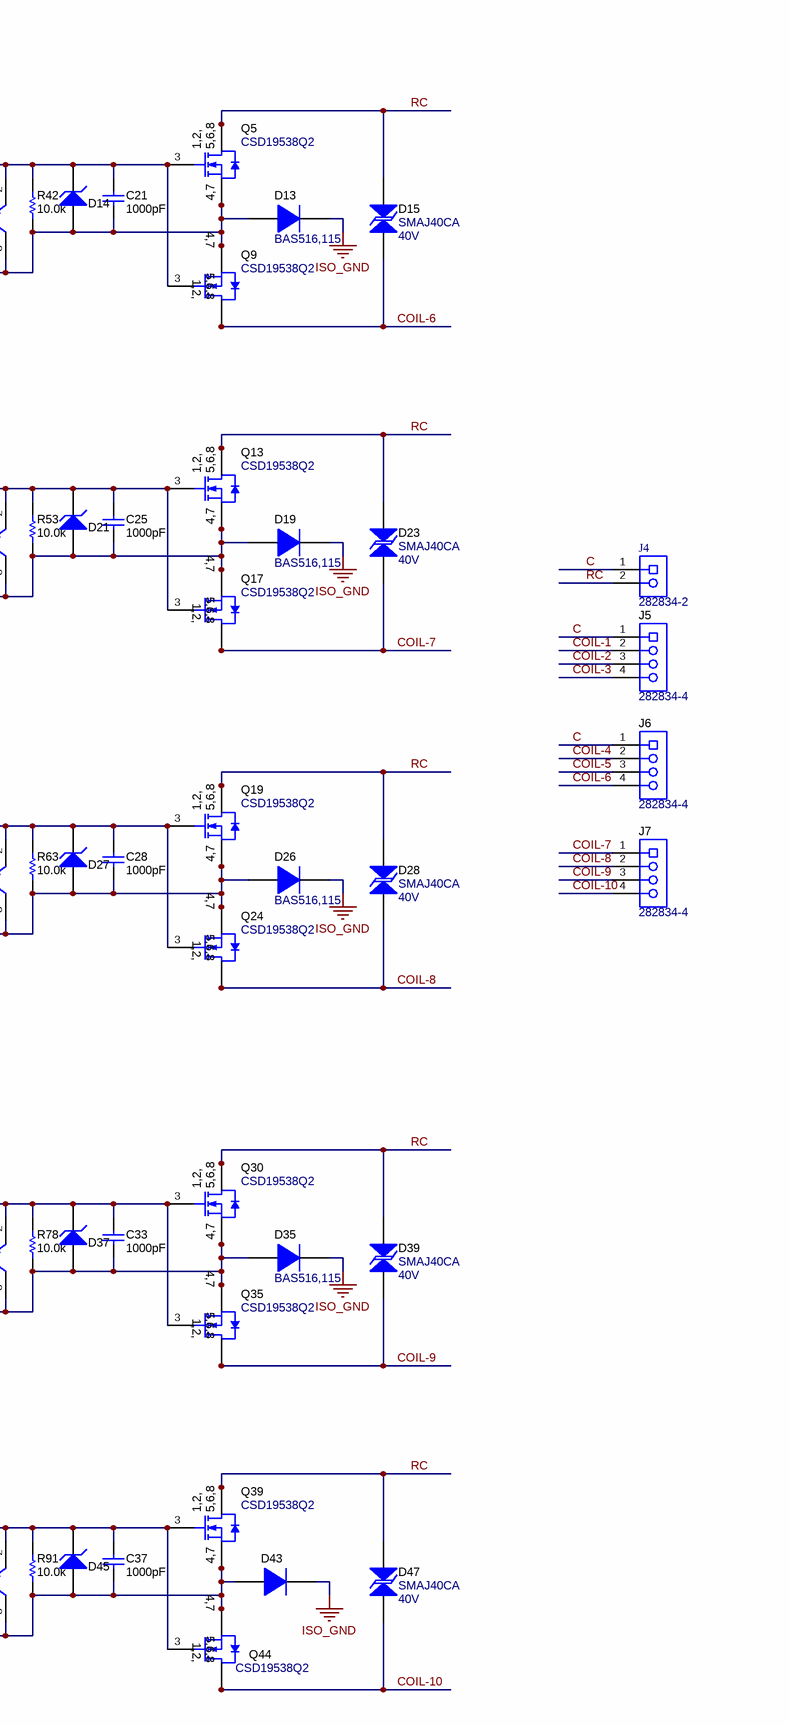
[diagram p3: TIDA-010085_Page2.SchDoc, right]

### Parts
C18  ValueDisplayed: 1000pF  [0402]  (hidden comment: 885012205061)
C19  ValueDisplayed: 1000pF  [0402]  (hidden comment: 885012205061)
C20  ValueDisplayed: 1000pF  [0402]  (hidden comment: 885012205061)
C21  ValueDisplayed: 1000pF  [0402]  (hidden comment: 885012205061)
C22  ValueDisplayed: 1000pF  [0402]  (hidden comment: 885012205061)
C23  ValueDisplayed: 1000pF  [0402]  (hidden comment: 885012205061)
C24  ValueDisplayed: 1000pF  [0402]  (hidden comment: 885012205061)
C25  ValueDisplayed: 1000pF  [0402]  (hidden comment: 885012205061)
C26  ValueDisplayed: 1000pF  [0402]  (hidden comment: 885012205061)
C27  ValueDisplayed: 1000pF  [0402]  (hidden comment: 885012205061)
C28  ValueDisplayed: 1000pF  [0402]  (hidden comment: 885012205061)
C29  ValueDisplayed: 1000pF  [0402]  (hidden comment: 885012205061)
C30  ValueDisplayed: 1000pF  [0402]  (hidden comment: 885012205061)
C31  ValueDisplayed: 1000pF  [0402]  (hidden comment: 885012205061)
C32  ValueDisplayed: 1000pF  [0402]  (hidden comment: 885012205061)
C33  ValueDisplayed: 1000pF  [0402]  (hidden comment: 885012205061)
C34  ValueDisplayed: 1000pF  [0402]  (hidden comment: 885012205061)
C35  ValueDisplayed: 1000pF  [0402]  (hidden comment: 885012205061)
C36  ValueDisplayed: 1000pF  [0402]  (hidden comment: 885012205061)
C37  ValueDisplayed: 1000pF  [0402]  (hidden comment: 885012205061)
D8  BAS516,115  [SOD-523]  (value not drawn)
D9  BAS516,115  [SOD-523]
D10  BAS516,115  [SOD-523]  (value not drawn)
D11  BZT585B12T-7  [SOD-523]  (value not drawn)
D12  SMAJ40CA  value 40V  [SMA_Bi]
D13  BAS516,115  [SOD-523]
D14  BZT585B12T-7  [SOD-523]  (value not drawn)
D15  SMAJ40CA  value 40V  [SMA_Bi]
D16  BAS516,115  [SOD-523]
D17  BAS516,115  [SOD-523]
D18  BAS516,115  [SOD-523]
D19  BAS516,115  [SOD-523]
D20  BZT585B12T-7  [SOD-523]  (value not drawn)
D21  BZT585B12T-7  [SOD-523]  (value not drawn)
D22  SMAJ40CA  value 40V  [SMA_Bi]
D23  SMAJ40CA  value 40V  [SMA_Bi]
D24  BAS516,115  [SOD-523]
D25  BAS516,115  [SOD-523]
D26  BAS516,115  [SOD-523]
D27  BZT585B12T-7  [SOD-523]  (value not drawn)
D28  SMAJ40CA  value 40V  [SMA_Bi]
D29  BAS516,115  [SOD-523]
D30  BZT585B12T-7  [SOD-523]  (value not drawn)
D31  SMAJ40CA  value 40V  [SMA_Bi]
D32  BAS516,115  [SOD-523]
D33  BAS516,115  [SOD-523]
D34  BAS516,115  [SOD-523]
D35  BAS516,115  [SOD-523]
D36  BZT585B12T-7  [SOD-523]  (value not drawn)
D37  BZT585B12T-7  [SOD-523]  (value not drawn)
D38  SMAJ40CA  value 40V  [SMA_Bi]
D39  SMAJ40CA  value 40V  [SMA_Bi]
D40  BAS516,115  [SOD-523]
D41  BAS516,115  [SOD-523]  (value not drawn)
D42  BAS516,115  [SOD-523]
D43  BAS516,115  [SOD-523]  (value not drawn)
D44  BZT585B12T-7  [SOD-523]  (value not drawn)
D45  BZT585B12T-7  [SOD-523]  (value not drawn)
D46  SMAJ40CA  value 40V  [SMA_Bi]
D47  SMAJ40CA  value 40V  [SMA_Bi]
J4  282834-2  [TEC_282834-2]
J5  282834-4  [TEC_282834-4]
J6  282834-4  [TEC_282834-4]
J7  282834-4  [TEC_282834-4]
Q2  MMBT2907AT-7-F  [SOT-523]  (value not drawn)
Q3  CSD19538Q2  [DQK0006C]
Q4  MMBT2907AT-7-F  [SOT-523]
Q5  CSD19538Q2  [DQK0006C]
Q6  MMBT2907AT-7-F  [SOT-523]  (value not drawn)
Q7  MMBT2907AT-7-F  [SOT-523]
Q8  CSD19538Q2  [DQK0006C]
Q9  CSD19538Q2  [DQK0006C]
Q10  MMBT2907AT-7-F  [SOT-523]
Q11  MMBT2907AT-7-F  [SOT-523]
Q12  CSD19538Q2  [DQK0006C]
Q13  CSD19538Q2  [DQK0006C]
Q14  MMBT2907AT-7-F  [SOT-523]
Q15  MMBT2907AT-7-F  [SOT-523]
Q16  CSD19538Q2  [DQK0006C]
Q17  CSD19538Q2  [DQK0006C]
Q18  MMBT2907AT-7-F  [SOT-523]
Q19  CSD19538Q2  [DQK0006C]
Q20  MMBT2907AT-7-F  [SOT-523]
Q21  CSD19538Q2  [DQK0006C]
Q22  NSVBC846BM3T5G  [SOT-416]
Q23  MMBT2907AT-7-F  [SOT-523]
Q24  CSD19538Q2  [DQK0006C]
Q25  MMBT2907AT-7-F  [SOT-523]
Q26  CSD19538Q2  [DQK0006C]
Q27  MMBT2907AT-7-F  [SOT-523]
Q28  MMBT2907AT-7-F  [SOT-523]
Q29  CSD19538Q2  [DQK0006C]
Q30  CSD19538Q2  [DQK0006C]
Q31  NSVBC846BM3T5G  [SOT-416]
Q32  MMBT2907AT-7-F  [SOT-523]
Q33  MMBT2907AT-7-F  [SOT-523]
Q34  CSD19538Q2  [DQK0006C]
Q35  CSD19538Q2  [DQK0006C]
Q36  MMBT2907AT-7-F  [SOT-523]
Q37  MMBT2907AT-7-F  [SOT-523]  (value not drawn)
Q38  CSD19538Q2  [DQK0006C]
Q39  CSD19538Q2  [DQK0006C]
Q40  NSVBC846BM3T5G  [SOT-416]
Q41  MMBT2907AT-7-F  [SOT-523]
Q42  MMBT2907AT-7-F  [SOT-523]  (value not drawn)
Q43  CSD19538Q2  [DQK0006C]
Q44  CSD19538Q2  [DQK0006C]
R32  ValueDisplayed: 10.0k  [0402]  (hidden comment: RMCF0402FT10K0)
R33  ValueDisplayed: 10.0k  [0402]  (hidden comment: RMCF0402FT10K0)
R34  ValueDisplayed: 475  [0402]  (hidden comment: CRCW0402475RFKED)
R35  ValueDisplayed: 100k  [0402]  (hidden comment: ERJ-2RKF1003X)
R36  ValueDisplayed: 475  [0402]  (hidden comment: CRCW0402475RFKED)
R37  ValueDisplayed: 100k  [0402]  (hidden comment: ERJ-2RKF1003X)
R38  ValueDisplayed: 0  [0402]  (hidden comment: RC0402JR-070RL)
R39  ValueDisplayed: 10.0k  [0402]  (hidden comment: RMCF0402FT10K0)
R40  ValueDisplayed: 0  [0402]  (hidden comment: RC0402JR-070RL)
R41  ValueDisplayed: 100k  [0402]  (hidden comment: ERJ-2RKF1003X)
R42  ValueDisplayed: 10.0k  [0402]  (hidden comment: RMCF0402FT10K0)
R43  ValueDisplayed: 100k  [0402]  (hidden comment: ERJ-2RKF1003X)
R44  ValueDisplayed: 10.0k  [0402]  (hidden comment: RMCF0402FT10K0)
R45  ValueDisplayed: 10.0k  [0402]  (hidden comment: RMCF0402FT10K0)
R46  ValueDisplayed: 475  [0402]  (hidden comment: CRCW0402475RFKED)
R47  ValueDisplayed: 475  [0402]  (hidden comment: CRCW0402475RFKED)
R48  ValueDisplayed: 100k  [0402]  (hidden comment: ERJ-2RKF1003X)
R49  ValueDisplayed: 100k  [0402]  (hidden comment: ERJ-2RKF1003X)
R50  ValueDisplayed: 0  [0402]  (hidden comment: RC0402JR-070RL)
R51  ValueDisplayed: 0  [0402]  (hidden comment: RC0402JR-070RL)
R52  ValueDisplayed: 10.0k  [0402]  (hidden comment: RMCF0402FT10K0)
R53  ValueDisplayed: 10.0k  [0402]  (hidden comment: RMCF0402FT10K0)
R54  ValueDisplayed: 100k  [0402]  (hidden comment: ERJ-2RKF1003X)
R55  ValueDisplayed: 100k  [0402]  (hidden comment: ERJ-2RKF1003X)
R56  ValueDisplayed: 10.0k  [0402]  (hidden comment: RMCF0402FT10K0)
R57  ValueDisplayed: 10.0k  [0402]  (hidden comment: RMCF0402FT10K0)
R58  ValueDisplayed: 475  [0402]  (hidden comment: CRCW0402475RFKED)
R59  ValueDisplayed: 100k  [0402]  (hidden comment: ERJ-2RKF1003X)
R60  ValueDisplayed: 475  [0402]  (hidden comment: CRCW0402475RFKED)
R61  ValueDisplayed: 100k  [0402]  (hidden comment: ERJ-2RKF1003X)
R62  ValueDisplayed: 0  [0402]  (hidden comment: RC0402JR-070RL)
R63  ValueDisplayed: 10.0k  [0402]  (hidden comment: RMCF0402FT10K0)
R64  ValueDisplayed: 0  [0402]  (hidden comment: RC0402JR-070RL)
R65  ValueDisplayed: 100k  [0402]  (hidden comment: ERJ-2RKF1003X)
R66  ValueDisplayed: 100k  [0402]  (hidden comment: ERJ-2RKF1003X)
R67  ValueDisplayed: 10.0k  [0402]  (hidden comment: RMCF0402FT10K0)
R68  ValueDisplayed: 100k  [0402]  (hidden comment: ERJ-2RKF1003X)
R69  ValueDisplayed: 10.0k  [0402]  (hidden comment: RMCF0402FT10K0)
R70  ValueDisplayed: 10.0k  [0402]  (hidden comment: RMCF0402FT10K0)
R71  ValueDisplayed: 475  [0402]  (hidden comment: CRCW0402475RFKED)
R72  ValueDisplayed: 475  [0402]  (hidden comment: CRCW0402475RFKED)
R73  ValueDisplayed: 100k  [0402]  (hidden comment: ERJ-2RKF1003X)
R74  ValueDisplayed: 100k  [0402]  (hidden comment: ERJ-2RKF1003X)
R75  ValueDisplayed: 0  [0402]  (hidden comment: RC0402JR-070RL)
R76  ValueDisplayed: 0  [0402]  (hidden comment: RC0402JR-070RL)
R77  ValueDisplayed: 10.0k  [0402]  (hidden comment: RMCF0402FT10K0)
R78  ValueDisplayed: 10.0k  [0402]  (hidden comment: RMCF0402FT10K0)
R79  ValueDisplayed: 100k  [0402]  (hidden comment: ERJ-2RKF1003X)
R80  ValueDisplayed: 100k  [0402]  (hidden comment: ERJ-2RKF1003X)
R81  ValueDisplayed: 100k  [0402]  (hidden comment: ERJ-2RKF1003X)
R82  ValueDisplayed: 10.0k  [0402]  (hidden comment: RMCF0402FT10K0)
R83  ValueDisplayed: 10.0k  [0402]  (hidden comment: RMCF0402FT10K0)
R84  ValueDisplayed: 475  [0402]  (hidden comment: CRCW0402475RFKED)
R85  ValueDisplayed: 475  [0402]  (hidden comment: CRCW0402475RFKED)
R86  ValueDisplayed: 100k  [0402]  (hidden comment: ERJ-2RKF1003X)
R87  ValueDisplayed: 100k  [0402]  (hidden comment: ERJ-2RKF1003X)
R88  ValueDisplayed: 0  [0402]  (hidden comment: RC0402JR-070RL)
R89  ValueDisplayed: 0  [0402]  (hidden comment: RC0402JR-070RL)
R90  ValueDisplayed: 10.0k  [0402]  (hidden comment: RMCF0402FT10K0)
R91  ValueDisplayed: 10.0k  [0402]  (hidden comment: RMCF0402FT10K0)
R92  ValueDisplayed: 100k  [0402]  (hidden comment: ERJ-2RKF1003X)
R93  ValueDisplayed: 100k  [0402]  (hidden comment: ERJ-2RKF1003X)
R94  ValueDisplayed: 100k  [0402]  (hidden comment: ERJ-2RKF1003X)

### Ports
OUT1 (in), OUT2 (in), OUT3 (in), OUT4 (in), OUT5 (in), OUT6 (in), OUT7 (in), OUT8 (in), OUT9 (in), OUT10 (in)

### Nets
ISO_GND: D10.1(K) D13.1(K) D18.1(K) D19.1(K) D26.1(K) D29.1(K) D34.1(K) D35.1(K) D42.1(K) D43.1(K) Q22.2(E) Q31.2(E) Q40.2(E)
VGD_ISO: C18.1 C19.1 C22.1 C23.1 C26.1 C27.1 C30.1 C31.1 C34.1 C35.1 Q2.2(E) Q4.2(E) Q10.2(E) Q11.2(E) Q18.2(E) Q20.2(E) Q27.2(E) Q28.2(E) Q36.2(E) Q37.2(E) R32.2 R33.2 R44.2 R45.2 R56.2 R57.2 R69.2 R70.2 R82.2 R83.2
C: J4.1 J5.1 J6.1
COIL-1: D12.1 J5.2 Q8.1(D) Q8.2(D) Q8.5(D) Q8.6(D) Q8.8(D)
COIL-2: D22.1 J5.3 Q16.1(D) Q16.2(D) Q16.5(D) Q16.6(D) Q16.8(D)
COIL-3: D31.1 J5.4 Q26.1(D) Q26.2(D) Q26.5(D) Q26.6(D) Q26.8(D)
COIL-4: D38.1 J6.2 Q34.1(D) Q34.2(D) Q34.5(D) Q34.6(D) Q34.8(D)
COIL-5: D46.1 J6.3 Q43.1(D) Q43.2(D) Q43.5(D) Q43.6(D) Q43.8(D)
COIL-6: D15.1 J6.4 Q9.1(D) Q9.2(D) Q9.5(D) Q9.6(D) Q9.8(D)
COIL-7: D23.1 J7.1 Q17.1(D) Q17.2(D) Q17.5(D) Q17.6(D) Q17.8(D)
COIL-8: D28.1 J7.2 Q24.1(D) Q24.2(D) Q24.5(D) Q24.6(D) Q24.8(D)
COIL-9: D39.1 J7.3 Q35.1(D) Q35.2(D) Q35.5(D) Q35.6(D) Q35.8(D)
COIL-10: D47.1 J7.4 Q44.1(D) Q44.2(D) Q44.5(D) Q44.6(D) Q44.8(D)
OUT1: R35.1 ; port OUT1
OUT2: R48.1 ; port OUT2
OUT3: R61.1 ; port OUT3
OUT4: R73.1 ; port OUT4
OUT5: R86.1 ; port OUT5
OUT6: R37.1 ; port OUT6
OUT7: R49.1 ; port OUT7
OUT8: R66.1 ; port OUT8
OUT9: R81.1 ; port OUT9
RC: D12.2 D15.2 D22.2 D23.2 D28.2 D31.2 D38.2 D39.2 D46.2 D47.2 J4.2 Q3.1(D) Q3.2(D) Q3.5(D) Q3.6(D) Q3.8(D) Q5.1(D) Q5.2(D) Q5.5(D) Q5.6(D) Q5.8(D) Q12.1(D) Q12.2(D) Q12.5(D) Q12.6(D) Q12.8(D) Q13.1(D) Q13.2(D) Q13.5(D) Q13.6(D) Q13.8(D) Q19.1(D) Q19.2(D) Q19.5(D) Q19.6(D) Q19.8(D) Q21.1(D) Q21.2(D) Q21.5(D) Q21.6(D) Q21.8(D) Q29.1(D) Q29.2(D) Q29.5(D) Q29.6(D) Q29.8(D) Q30.1(D) Q30.2(D) Q30.5(D) Q30.6(D) Q30.8(D) Q38.1(D) Q38.2(D) Q38.5(D) Q38.6(D) Q38.8(D) Q39.1(D) Q39.2(D) Q39.5(D) Q39.6(D) Q39.8(D)
NetC18_2: C18.2 Q2.1(B) R32.1 R35.2
NetC19_2: C19.2 Q4.1(B) R33.1 R37.2
NetC20_1: C20.1 D8.1(K) D11.1(K) Q3.3(G) Q6.2(E) Q8.3(G) R39.2
NetC20_2: C20.2 D10.2(A) D11.2(A) Q3.4(S) Q3.7(S) Q6.3(C) Q8.4(S) Q8.7(S) R39.1 R41.1
NetC21_1: C21.1 D9.1(K) D14.1(K) Q5.3(G) Q7.2(E) Q9.3(G) R42.2
NetC21_2: C21.2 D13.2(A) D14.2(A) Q5.4(S) Q5.7(S) Q7.3(C) Q9.4(S) Q9.7(S) R42.1 R43.1
NetC22_2: C22.2 Q10.1(B) R44.1 R48.2
NetC23_2: C23.2 Q11.1(B) R45.1 R49.2
NetC24_1: C24.1 D16.1(K) D20.1(K) Q12.3(G) Q14.2(E) Q16.3(G) R52.2
NetC24_2: C24.2 D18.2(A) D20.2(A) Q12.4(S) Q12.7(S) Q14.3(C) Q16.4(S) Q16.7(S) R52.1 R54.1
NetC25_1: C25.1 D17.1(K) D21.1(K) Q13.3(G) Q15.2(E) Q17.3(G) R53.2
NetC25_2: C25.2 D19.2(A) D21.2(A) Q13.4(S) Q13.7(S) Q15.3(C) Q17.4(S) Q17.7(S) R53.1 R55.1
NetC26_2: C26.2 Q18.1(B) R56.1 R59.2
NetC27_2: C27.2 Q20.1(B) R57.1 R61.2
NetC28_1: C28.1 D24.1(K) D27.1(K) Q19.3(G) Q23.2(E) Q24.3(G) R63.2
NetC28_2: C28.2 D26.2(A) D27.2(A) Q19.4(S) Q19.7(S) Q23.3(C) Q24.4(S) Q24.7(S) R63.1 R65.1
NetC29_1: C29.1 D25.1(K) D30.1(K) Q21.3(G) Q25.2(E) Q26.3(G) R67.2
NetC29_2: C29.2 D29.2(A) D30.2(A) Q21.4(S) Q21.7(S) Q25.3(C) Q26.4(S) Q26.7(S) R67.1 R68.1
NetC30_2: C30.2 Q27.1(B) R69.1 R73.2
NetC31_2: C31.2 Q28.1(B) R70.1 R74.2
NetC32_1: C32.1 D32.1(K) D36.1(K) Q29.3(G) Q32.2(E) Q34.3(G) R77.2
NetC32_2: C32.2 D34.2(A) D36.2(A) Q29.4(S) Q29.7(S) Q32.3(C) Q34.4(S) Q34.7(S) R77.1 R79.1
NetC33_1: C33.1 D33.1(K) D37.1(K) Q30.3(G) Q33.2(E) Q35.3(G) R78.2
NetC33_2: C33.2 D35.2(A) D37.2(A) Q30.4(S) Q30.7(S) Q33.3(C) Q35.4(S) Q35.7(S) R78.1 R80.1
NetC34_2: C34.2 Q36.1(B) R82.1 R86.2
NetC35_2: C35.2 Q37.1(B) R83.1 R87.2
NetC36_1: C36.1 D40.1(K) D44.1(K) Q38.3(G) Q41.2(E) Q43.3(G) R90.2
NetC36_2: C36.2 D42.2(A) D44.2(A) Q38.4(S) Q38.7(S) Q41.3(C) Q43.4(S) Q43.7(S) R90.1 R92.1
NetC37_1: C37.1 D41.1(K) D45.1(K) Q39.3(G) Q42.2(E) Q44.3(G) R91.2
NetC37_2: C37.2 D43.2(A) D45.2(A) Q39.4(S) Q39.7(S) Q42.3(C) Q44.4(S) Q44.7(S) R91.1 R93.1
NetD8_2: D8.2(A) R34.2 R38.2 R41.2
NetD9_2: D9.2(A) R36.2 R40.2 R43.2
NetD16_2: D16.2(A) R46.2 R50.2 R54.2
NetD17_2: D17.2(A) R47.2 R51.2 R55.2
NetD24_2: D24.2(A) R58.2 R62.2 R65.2
NetD25_2: D25.2(A) R60.2 R64.2 R68.2
NetD32_2: D32.2(A) R71.2 R75.2 R79.2
NetD33_2: D33.2(A) R72.2 R76.2 R80.2
NetD40_2: D40.2(A) R84.2 R88.2 R92.2
NetD41_2: D41.2(A) R85.2 R89.2 R93.2
NetQ2_3: Q2.3(C) R34.1
NetQ4_3: Q4.3(C) R36.1
NetQ6_1: Q6.1(B) R38.1
NetQ7_1: Q7.1(B) R40.1
NetQ10_3: Q10.3(C) R46.1
NetQ11_3: Q11.3(C) R47.1
NetQ14_1: Q14.1(B) R50.1
NetQ15_1: Q15.1(B) R51.1
NetQ18_3: Q18.3(C) R58.1
NetQ20_3: Q20.3(C) R60.1
NetQ22_1: Q22.1(B) R66.2
NetQ22_3: Q22.3(C) R59.1
NetQ23_1: Q23.1(B) R62.1
NetQ25_1: Q25.1(B) R64.1
NetQ27_3: Q27.3(C) R71.1
NetQ28_3: Q28.3(C) R72.1
NetQ31_1: Q31.1(B) R81.2
NetQ31_3: Q31.3(C) R74.1
NetQ32_1: Q32.1(B) R75.1
NetQ33_1: Q33.1(B) R76.1
NetQ36_3: Q36.3(C) R84.1
NetQ37_3: Q37.3(C) R85.1
NetQ40_1: Q40.1(B) R94.2
NetQ40_3: Q40.3(C) R87.1
NetQ41_1: Q41.1(B) R88.1
NetQ42_1: Q42.1(B) R89.1

Not connected (* = marked no-connect by the designer): R94 1

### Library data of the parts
C18-C37 = CMP-0006231-2: as C5 on sheet TIDA-010085_Page1
D8-D10 D13 D16-D19 D24-D26 D29 D32-D35 D40-D43 = CMP-0076979-3: Diode, Switching, 100 V, 0.25 A, SOD-523; Manufacturer: Nexperia; Value: 100V; SizeAreaWB_mm2: 5.13; Vf_V: 1.25V; SizeArea_mm2: 1.53; SizeY_mm: 0.9; Green_Lifecycle: Not Set; AEC Category: Q101; SizeX_mm: 1.7; Green_REACh: Incomplete; Io_A: 250mA; TJmax_C: 150°C; SizeZ_mm: 0.65; Value1: 0.25A
D11 D14 D20 D21 D27 D30 D36 D37 D44 D45 = CMP-0005888-2: as D2 on sheet TIDA-010085_Page1
D12 D15 D22 D23 D28 D31 D38 D39 D46 D47 = CMP-0085018-1: Diode, TVS, Bi, 40 V, 64.5 Vc, 400 W, 6.2 A, SMA (non-polarized); Manufacturer: Littelfuse; SizeY_mm: 2.575; SizeZ_mm: 2.65; RJA_CperW: 120; Vc: 64.5V; SizeX_mm: 5.075; SizeArea_mm2: 13.068125; Vbr_Max: 49.1V; Ppk: 400W; Ipp: 6.2A; Vbr_Min: 44.4V; AEC Category: Q101; SizeAreaWB_mm2: 32.368125; AEC Qualified: N
J4 = CMP-0054974-1: as J1 on sheet TIDA-010085_Page1
J5-J7 = CMP-0054976-1: Terminal Block, 100mil, 4X1 TH; Manufacturer: TE Connectivity; CT: TRUE; Green_REACh: Passed; CNHeader: FALSE; Green_Lifecycle: Active
Q2 Q4 Q6 Q7 Q10 Q11 Q14 Q15 Q18 Q20 Q23 Q25 Q27 Q28 Q32 Q33 Q36 Q37 Q41 Q42 = CMP-0000362-2: Transistor, PNP, 60 V, 0.6 A, AEC-Q101, SOT-523; Manufacturer: Diodes Inc.; TaMax_C: 150°C; Value2: 300; Value1: 0.6 A; Vcesat1_V: 400mV; SizeX_mm: 1.6; TaMin_C: -55°C; IcRated_A: 600mA; CompType: BJT; SizeZ_mm: 0.8; AEC Qualified: Y; Value: 60 V; SizeArea_mm2: 2.56; NPN: 0; Vceo_V: 60V; PNP: 1; AEC Category: Q101; SizeAreaWB_mm2: 6.76; U/M: EA
Q3 Q5 Q8 Q9 Q12 Q13 Q16 Q17 Q19 Q21 Q24 Q26 Q29 Q30 Q34 Q35 Q38 Q39 Q43 Q44 = CMP-0000968-1: MOSFET, N-CH, 100 V, 4.5 A, DQK0006C (WSON-6); Alternate Manufacturer: None; Manufacturer: Texas Instruments; SizeZ_mm: 0.8; ChType: N; VdsMax_V: 100V; SizeX_mm: 2; SizeAreaWB_mm2: 9; Vgs_V: 20V; Value: 100V; SizeArea_mm2: 4; AEC Category: Q101; IdsMax_A: 4.5A; U/M: EA
Q22 Q31 Q40 = CMP-0000485-2: Bipolar (BJT) Transistor NPN 65V 100mA 100MHz 265mW Surface Mount SOT-723; Manufacturer: ON Semiconductor; TaMax_C: 150°C; Value1: 0.1 A; Vcesat1_V: 600mV; TaMin_C: -55°C; AEC Qualified: Y; NPN: 1; PNP: 0; AEC Category: Q101; U/M: EA
R32 R33 R39 R42 R44 R45 R52 R53 R56 R57 R63 R67 R69 R70 R77 R78 R82 R83 R90 R91 = CMP-0026754-1: as R3 on sheet TIDA-010085_Page1
R34 R36 R46 R47 R58 R60 R71 R72 R84 R85 = CMP-0026394-2: RES, 475, 1%, 0.063 W, AEC-Q200 Grade 0, 0402; Manufacturer: Vishay-Dale; Power_W: 63mW; TempCo: 100 ppm/C; Value_Code: 475R; Value: 475; EIA_Code: E96; SizeX_mm: 1; SizeY_mm: 0.5; SizeZ_mm: 0.6; Value2: 0.063W; AEC Qualified: Y; VDC_V: 50V; AEC Category: Q200; AEC Grade: 0
R35 R37 R41 R43 R48 R49 R54 R55 R59 R61 R65 R66 R68 R73 R74 R79-R81 R86 R87 R92-R94 = CMP-0026659-1: as R18 on sheet TIDA-010085_Page1
R38 R40 R50 R51 R62 R64 R75 R76 R88 R89 = CMP-0027004-2: as R2 on sheet TIDA-010085_Page1

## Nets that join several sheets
ISO_GND: TIDA-010085_Page1 (16 pins), TIDA-010085_Page2 (13 pins)
VGD_ISO: TIDA-010085_Page1 (C15.1 R8.2 R9.1 U6.9), TIDA-010085_Page2 (30 pins)
OUT1: TIDA-010085_Page1 (U6.10), TIDA-010085_Page2 (R35.1)
OUT2: TIDA-010085_Page1 (U6.11), TIDA-010085_Page2 (R48.1)
OUT3: TIDA-010085_Page1 (U6.12), TIDA-010085_Page2 (R61.1)
OUT4: TIDA-010085_Page1 (U6.13), TIDA-010085_Page2 (R73.1)
OUT5: TIDA-010085_Page1 (U6.14), TIDA-010085_Page2 (R86.1)
OUT6: TIDA-010085_Page1 (U6.15), TIDA-010085_Page2 (R37.1)
OUT7: TIDA-010085_Page1 (U6.16), TIDA-010085_Page2 (R49.1)
OUT8: TIDA-010085_Page1 (U7.12), TIDA-010085_Page2 (R66.1)
OUT9: TIDA-010085_Page1 (U7.13), TIDA-010085_Page2 (R81.1)

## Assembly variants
001: not fitted C3 C7 R4 R9 R10 R11 R26 R27 U2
